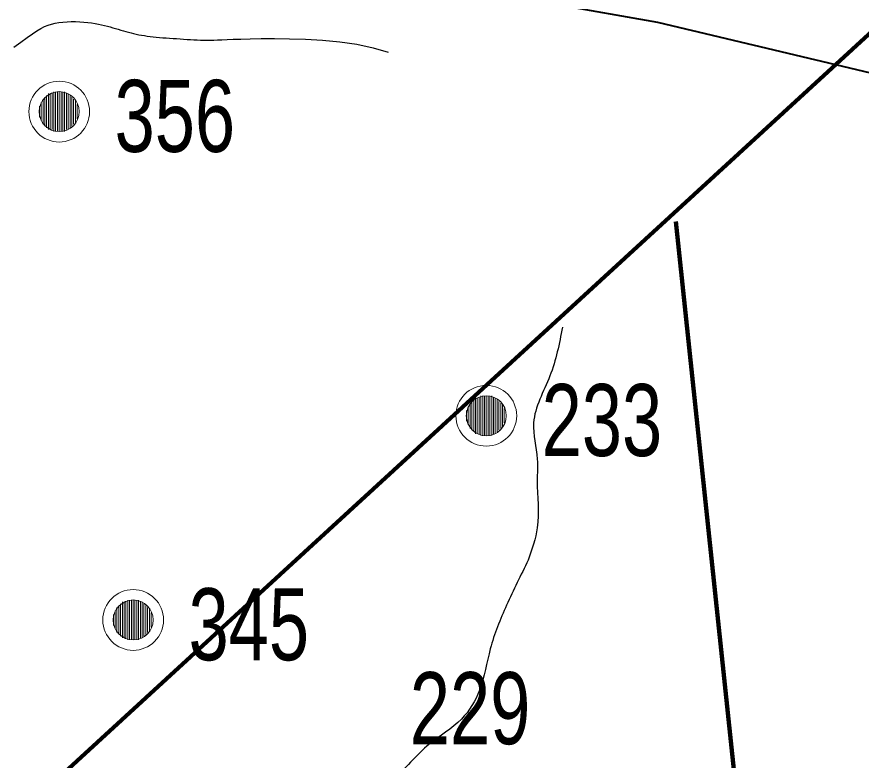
# Model space of a CAD drawing. Extents: x 553962 to 842807, y 8883888 to 9032388.
# Drawn here: x 713634 to 718324, y 8956639 to 8960766 of the extents above; entities that cross this region are included whole.
import ezdxf

# ---------------------------------------------------------------- set-up
doc = ezdxf.new("R2010")
doc.units = 0
doc.header["$LTSCALE"] = 160
for name, color, linetype, lineweight in [('15', 7, 'Continuous', 25), ('21', 7, 'Continuous', 25), ('27', 7, 'Continuous', 90), ('32', 7, 'Continuous', 13)]:
    doc.layers.add(name, color=color, linetype=linetype, lineweight=lineweight)

msp = doc.modelspace()

# ---------------------------------------------------------------- linework, layer by layer
at = {"layer": '15', "lineweight": 40}
msp.add_lwpolyline([(710551.5, 8961397.1), (711177.1, 8961501.2), (712016, 8961727.1), (712359, 8961724.2), (713550.7, 8961508.2), (716056.5, 8960938), (717193.5, 8960736.2), (719630.3, 8960157.3)], dxfattribs=at)
at = {"layer": '21'}
for points in [[(713767.8, 8960701.6), (713788.2, 8960712.2), (713807.5, 8960720.4), (713826.5, 8960726.6), (713846.2, 8960731.3), (713867.2, 8960734.9), (713889.5, 8960737.5), (713912.7, 8960739.1), (713936.3, 8960739.8), (713960.1, 8960739.8), (713983.6, 8960739), (714006.5, 8960737.5), (714028.5, 8960735.5), (714049.1, 8960732.9), (714068.6, 8960729.9), (714087, 8960726.5), (714104.5, 8960722.7), (714121.2, 8960718.7), (714137.2, 8960714.5), (714152.6, 8960710.2), (714167.7, 8960705.8), (714182.5, 8960701.4), (714197.1, 8960697.1), (714211.5, 8960692.8), (714225.7, 8960688.6), (714240, 8960684.5), (714254.2, 8960680.7), (714268.4, 8960677), (714282.7, 8960673.5), (714297.2, 8960670.3), (714311.9, 8960667.4), (714326.8, 8960664.7), (714342.1, 8960662.2), (714357.7, 8960659.8), (714373.9, 8960657.7), (714390.6, 8960655.8), (714407.8, 8960653.9), (714425.8, 8960652.2), (714444.2, 8960650.7), (714463.1, 8960649.2)], [(713616.3, 8960597.2), (713656, 8960626.3), (713690.3, 8960650.9), (713719.8, 8960671.4), (713745.3, 8960688.2), (713767.8, 8960701.6)], [(714463.1, 8960649.2), (714482.3, 8960647.8), (714501.8, 8960646.4), (714521.3, 8960645.2), (714540.8, 8960643.9), (714560.1, 8960642.7), (714579.2, 8960641.4), (714598, 8960640.3), (714616.7, 8960639.2), (714635.3, 8960638.3), (714653.8, 8960637.6), (714672.3, 8960637.1), (714690.9, 8960636.9), (714709.5, 8960637.1), (714728.5, 8960637.7), (714749.1, 8960638.5), (714772.9, 8960639.6), (714801.3, 8960640.8), (714835.9, 8960642.1), (714878.1, 8960643.3), (714929.4, 8960644.4), (714991.4, 8960645.3), (715064.8, 8960645.7), (715147.8, 8960645), (715237.6, 8960642.3), (715331.6, 8960636.8), (715427.3, 8960627.7), (715521.9, 8960614.1), (715612.9, 8960595.2), (715697.6, 8960570.2)]]:
    msp.add_lwpolyline(points, dxfattribs=at)
for points in [[(716665.2, 8959042.7), (716595.1, 8958771.9), (716504.9, 8958511.2), (716524.9, 8958310.6), (716524.9, 8958190.3), (716524.9, 8957929.6), (716474.8, 8957749)], [(716474.8, 8957749), (716354.5, 8957498.3), (716264.3, 8957257.6), (716204.2, 8957027), (716103.9, 8956866.5), (715923.5, 8956726.1), (715743.1, 8956545.6), (715462.4, 8956294.9), (715171.8, 8956004.1), (715115.4, 8955955.8)]]:
    msp.add_spline(points, degree=3, dxfattribs=at)
at = {"layer": '27'}
for points in [[(705081.2, 8958366.8), (705509.2, 8948874.2), (720755.9, 8962863.6), (723053.6, 8963740.6)], [(717295.3, 8959630.3), (717636.9, 8956393.6), (717537.2, 8955887), (718376.1, 8955487), (718808.6, 8955185.8), (719472.1, 8954177.6), (719984.6, 8952814.2), (721077.3, 8952390.4), (721486.8, 8951456.6), (721666.8, 8950799.8), (721718.4, 8950547.1), (727920.4, 8947850.3), (733274.5, 8948007.9), (737635.8, 8948628.8)]]:
    msp.add_lwpolyline(points, dxfattribs=at)
at = {"layer": '32'}
for p, q in [((713839, 8960350), (713839, 8960130)), ((713849, 8960350), (713849, 8960130)), ((713859, 8960350), (713859, 8960130)), ((713869, 8960350), (713869, 8960130)), ((713879, 8960350), (713879, 8960130)), ((713889, 8960350), (713889, 8960130)), ((713899, 8960350), (713899, 8960130)), ((713779, 8960310), (713779, 8960170)), ((713789, 8960320), (713789, 8960160)), ((713799, 8960330), (713799, 8960150)), ((713809, 8960340), (713809, 8960140)), ((713819, 8960340), (713819, 8960140)), ((713829, 8960340), (713829, 8960140)), ((713909, 8960340), (713909, 8960140)), ((713919, 8960340), (713919, 8960140)), ((713929, 8960330), (713929, 8960150)), ((713939, 8960320), (713939, 8960160)), ((713949, 8960310), (713949, 8960170)), ((713759, 8960270), (713759, 8960210)), ((713769, 8960290), (713769, 8960190)), ((713959, 8960300), (713959, 8960180)), ((713969, 8960280), (713969, 8960200)), ((716152, 8958621), (716152, 8958481)), ((716162, 8958631), (716162, 8958471)), ((716172, 8958641), (716172, 8958461)), ((716182, 8958651), (716182, 8958451)), ((716192, 8958651), (716192, 8958451)), ((716202, 8958651), (716202, 8958451)), ((716212, 8958661), (716212, 8958441)), ((716222, 8958661), (716222, 8958441)), ((716232, 8958661), (716232, 8958441)), ((716242, 8958661), (716242, 8958441)), ((716252, 8958661), (716252, 8958441)), ((716262, 8958661), (716262, 8958441)), ((716272, 8958661), (716272, 8958441)), ((716282, 8958651), (716282, 8958451)), ((716292, 8958651), (716292, 8958451)), ((716302, 8958641), (716302, 8958461)), ((716312, 8958631), (716312, 8958471)), ((716322, 8958621), (716322, 8958481)), ((716132, 8958581), (716132, 8958521)), ((716142, 8958601), (716142, 8958501)), ((716332, 8958611), (716332, 8958491)), ((716342, 8958591), (716342, 8958511)), ((714200, 8957497), (714200, 8957337)), ((714210, 8957507), (714210, 8957327)), ((714220, 8957517), (714220, 8957317)), ((714230, 8957517), (714230, 8957317)), ((714240, 8957517), (714240, 8957317)), ((714250, 8957527), (714250, 8957307)), ((714260, 8957527), (714260, 8957307)), ((714270, 8957527), (714270, 8957307)), ((714280, 8957527), (714280, 8957307)), ((714290, 8957527), (714290, 8957307)), ((714300, 8957527), (714300, 8957307)), ((714310, 8957527), (714310, 8957307)), ((714320, 8957517), (714320, 8957317)), ((714330, 8957517), (714330, 8957317)), ((714340, 8957507), (714340, 8957327)), ((714350, 8957497), (714350, 8957337)), ((714170, 8957447), (714170, 8957387)), ((714180, 8957467), (714180, 8957367)), ((714190, 8957487), (714190, 8957347)), ((714360, 8957487), (714360, 8957347)), ((714370, 8957477), (714370, 8957357)), ((714380, 8957457), (714380, 8957377))]:
    msp.add_line(p, q, dxfattribs=at)
for centre, radius in [((713869, 8960240), 168.7), ((713869, 8960240), 111), ((716242, 8958551), 168.7), ((716242, 8958551), 111), ((714280, 8957417), 168.7), ((714280, 8957417), 111)]:
    msp.add_circle(centre, radius, dxfattribs=at)

# ---------------------------------------------------------------- texts
at = {"layer": '32', "width": 0.75}
for s, p in [('356', (714176.8, 8960016.3)), ('233', (716549.8, 8958327.3)), ('345', (714587.8, 8957193.3)), ('229', (715817.3, 8956727.1))]:
    msp.add_text(s, height=400, dxfattribs=at).set_placement(p)

doc.saveas('drawing.dxf')
